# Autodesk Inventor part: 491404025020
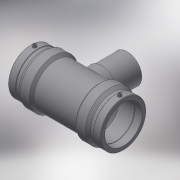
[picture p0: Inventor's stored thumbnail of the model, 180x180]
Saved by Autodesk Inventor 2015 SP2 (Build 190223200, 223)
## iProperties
Created: 2017-06
Part Number: 491404025020
Material: Generic
Description: PLASSON REDUCING TEE 25x20x25
Document SubType Name: Modeling
Designer: KIM
Mass: 113.024 g
Surface Area: 326.229 cm^2
Volume: 113.024 cm^3
Density: 1 g/cm^3
Appearance: Default
Author: KIM
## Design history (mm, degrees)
derived "491404.ipt"
feature "Solid1::491404.ipt"
tag "TaggingFeature1"
body "Solid1"
other parameters: "d0" = 104, "d1" = 25, "d2" = 44, "d3" = 39, "d4" = 20.8, "d5" = 39.6, "d6" = 23.75, "d7" = 25, "d8" = 168 deg, "d10" = 15.6, "d11" = 5.2, "d13" = 104, "d14" = 17.6296, "d17" = 22.5, "d18" = 25, "d19" = 3.52592, "d20" = 168 deg, "d22" = 40.92, "d23" = 44, "d25" = 135 deg, "d26" = 72.8, "d29" = 43, "d30" = 15, "d31" = 41.6, "d34" = 5 deg, "d35" = 15, "d39" = 5 deg, "d41" = 4, "d42" = 14, "d43" = 0, "d45" = 4, "d46" = 6, "d47" = 0, "d48" = -66, "d51" = 0, "d52" = 16, "d54" = 0, "d55" = 39.6, "d56" = 44, "d57" = 36.4, "d58" = 135 deg, "d59" = 39, "d60" = 39, "d61" = 135 deg, "d62" = 66, "d72" = 47.32, "d73" = 23.66, "d74" = -66, "d75" = 21, "d77" = 0, "d78" = 16, "d80" = 0, "d82" = 44, "d83" = 0, "d84" = 3, "d85" = 0, "d86" = 13, "d87" = 40.1016, "d88" = 5.2, "d89" = 3, "d90" = 0, "d_" = 25, "L_" = 104, "L_1" = 39, "D_" = 44, "A_" = 43, "d_2" = 12, "H_" = 66
